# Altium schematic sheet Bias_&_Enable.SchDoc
size 431 x 279 mm; Date: Not shown in title block; ApprovedBy: Not shown in title block; CheckedBy: Not shown in title block; Author: Not shown in title block; CompanyName: Not shown in title block; Engineer: Not shown in title block; Organization: Not shown in title block; Address1: Not shown in title block; Address2: Not shown in title block; Address3: Not shown in title block; Address4: Not shown in title block; DocumentNumber: 3; Revision: Use project parameter SCH_Rev; SheetNumber: 4; SheetTotal: 4; PageSetup: Record=PageOptions¦CenterHorizontal=True¦CenterVertical=True¦PrintScale=1.00¦XCorrection=1.00¦YCorrection=1.00¦PrintKind=0¦BorderSize=5000000¦LeftOffset=0¦BottomOffset=0¦Orientation=2¦PaperLength=1000¦PaperWidth=1000¦Scale=100¦PaperSource=15¦PrintQuality=600¦MediaType=1¦DitherType=10¦PaperKind=Letter¦PrintScaleMode=1
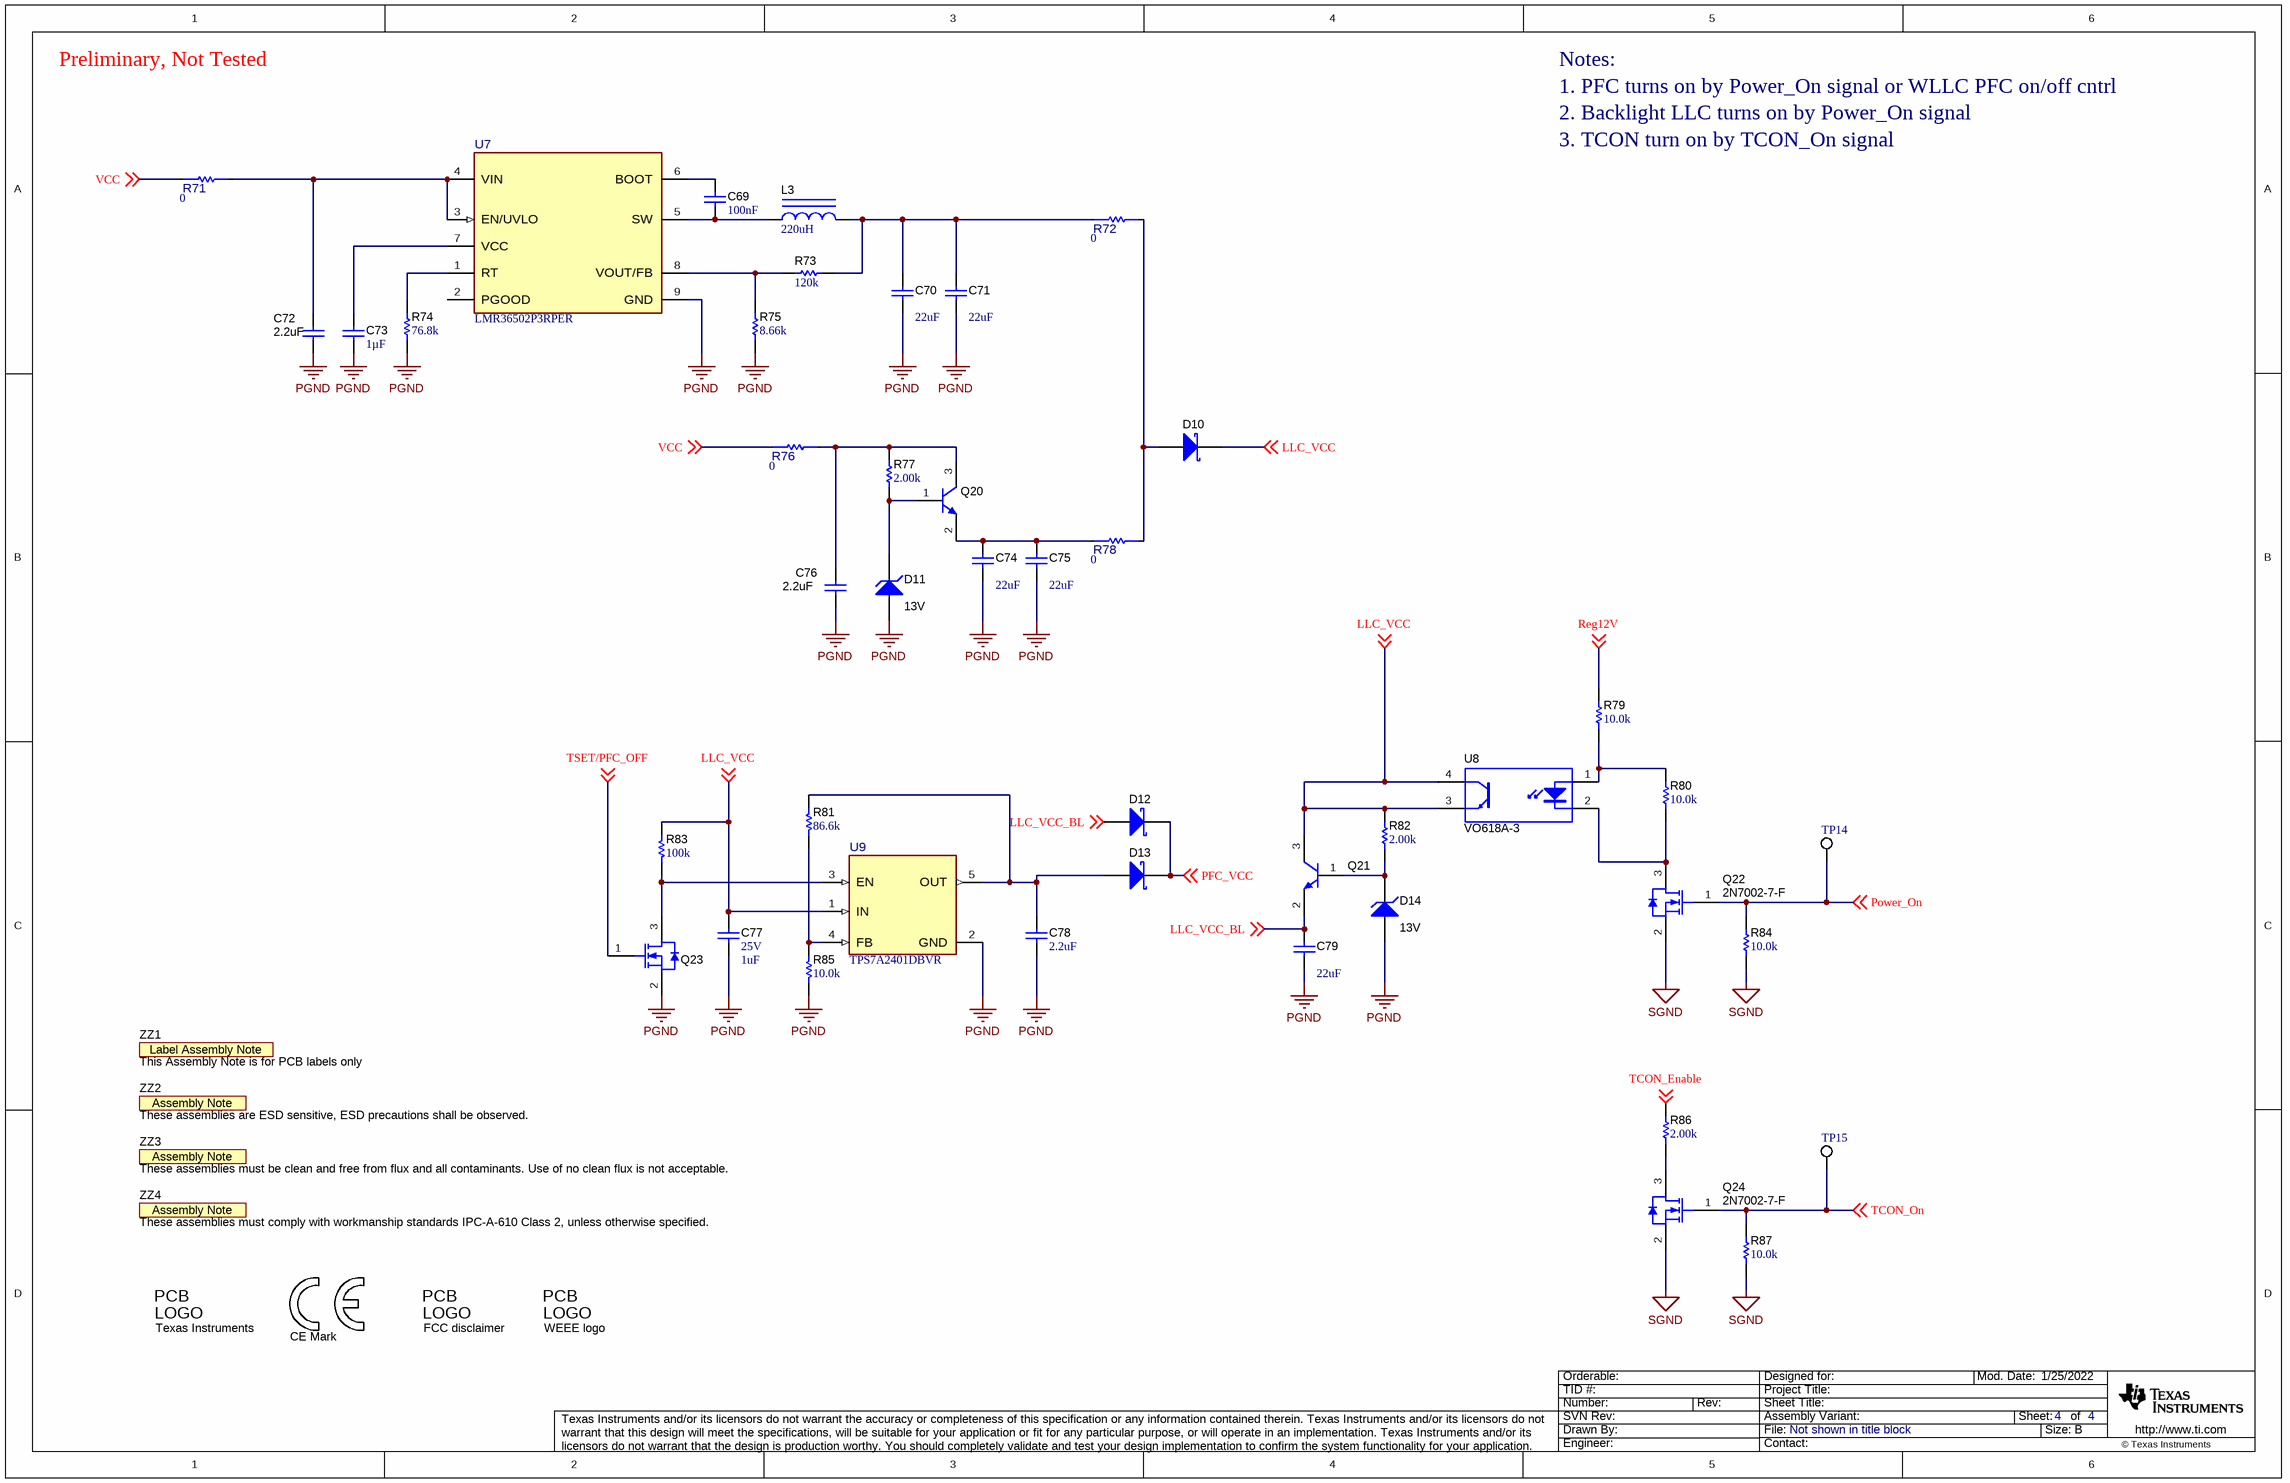
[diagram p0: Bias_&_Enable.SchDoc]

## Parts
C69  Cap_F: 100nF  [0603]  (hidden comment: C0603X104K3RACTU)
C70  ValueDisplayed: 22uF  [1210_270]  (hidden comment: GRM32ER61E226KE15L)
C71  ValueDisplayed: 22uF  [1210_270]  (hidden comment: GRM32ER61E226KE15L)
C72  ValueDisplayed: 2.2uF  [0805L]  (hidden comment: C2012X7R1V225K085AC)
C73  Cap_F: 1µF  [0603]  (hidden comment: C1608X7R1V105K080AC)
C74  ValueDisplayed: 22uF  [1210_270]  (hidden comment: GRM32ER61E226KE15L)
C75  ValueDisplayed: 22uF  [1210_270]  (hidden comment: GRM32ER61E226KE15L)
C76  ValueDisplayed: 2.2uF  [0805L]  (hidden comment: C2012X7R1V225K085AC)
C77  VDC_V: 25V  ValueDisplayed: 1uF  [0603]  (hidden comment: C1608X5R1E105K080AC)
C78  ValueDisplayed: 2.2uF  [0805_HV]  (hidden comment: Capacitor)
C79  ValueDisplayed: 22uF  [1210_270]  (hidden comment: GRM32ER61E226KE15L)
D10  BAT54WS-7-F  [SOD-323]  (value not drawn)
D11  value 13V  [SOD-123]  (hidden comment: MMSZ5243B-7-F)
D12  BAT54WS-7-F  [SOD-323]  (value not drawn)
D13  BAT54WS-7-F  [SOD-323]  (value not drawn)
D14  value 13V  [SOD-123]  (hidden comment: MMSZ5243B-7-F)
L3  ValueDisplayed: 220uH  [MSS5121]  (hidden comment: MSS5121-224MLB)
Logo1  CE Mark  [CE_Mark_5mm]  (no BOM)
Logo2  Texas Instruments  [TI_Stacked_Overlay_Small]  (no BOM)
Logo3  FCC disclaimer  [FCC_disclaimer]  (no BOM)
Logo4  WEEE logo  [WEEE_Minimum]  (no BOM)
Q20  MMBTA05LT1G  [SOT-23]  (value not drawn)
Q21  MMBTA05LT1G  [SOT-23]  (value not drawn)
Q22  2N7002-7-F  [SOT-23]
Q23  2N7002-7-F  [SOT-23]  (value not drawn)
Q24  2N7002-7-F  [SOT-23]
R71  value 0  [FP-RMCF1206ZT0R00_1206-MFG]  (hidden comment: RMCF1206ZT0R00)
R72  value 0  [FP-RMCF1206ZT0R00_1206-MFG]  (hidden comment: RMCF1206ZT0R00)
R73  ValueDisplayed: 120k  [0603]  (hidden comment: RC0603FR-07120KL)
R74  ValueDisplayed: 76.8k  [0603]  (hidden comment: RC0603FR-0776K8L)
R75  ValueDisplayed: 8.66k  [0603]  (hidden comment: RC0603FR-078K66L)
R76  value 0  [FP-RMCF1206ZT0R00_1206-MFG]  (hidden comment: RMCF1206ZT0R00)
R77  ValueDisplayed: 2.00k  [0603]  (hidden comment: RC0603FR-072KL)
R78  value 0  [FP-RMCF1206ZT0R00_1206-MFG]  (hidden comment: RMCF1206ZT0R00)
R79  ValueDisplayed: 10.0k  [0603]  (hidden comment: M55342K12B10E0T)
R80  ValueDisplayed: 10.0k  [0603]  (hidden comment: M55342K12B10E0T)
R81  ValueDisplayed: 86.6k  [0603]  (hidden comment: RC0603FR-0786K6L)
R82  ValueDisplayed: 2.00k  [0603]  (hidden comment: RC0603FR-072KL)
R83  ValueDisplayed: 100k  [0603]  (hidden comment: RC0603FR-07100KL)
R84  ValueDisplayed: 10.0k  [0603]  (hidden comment: M55342K12B10E0T)
R85  ValueDisplayed: 10.0k  [0603]  (hidden comment: M55342K12B10E0T)
R86  ValueDisplayed: 2.00k  [0603]  (hidden comment: RC0603FR-072KL)
R87  ValueDisplayed: 10.0k  [0603]  (hidden comment: M55342K12B10E0T)
TP14  5012  [Keystone5012]  (value not drawn)
TP15  5012  [Keystone5012]  (value not drawn)
U7  LMR36502P3RPER  [RPE0009B-MFG]
U8  VO618A-3  [DIP-4]
U9  TPS7A2401DBVR  [DBV0005A-MFG]
ZZ1  This Assembly Note is for PCB labels only  [AssemblyNoteLabel]  (no BOM)
ZZ2  These assemblies are ESD sensitive, ESD precautions shall be observed.  [AssemblyNote]  (no BOM)
ZZ3  These assemblies must be clean and free from flux and all contaminants. Use of no clean flux is not acceptable.  [AssemblyNote]  (no BOM)
ZZ4  These assemblies must comply with workmanship standards IPC-A-610 Class 2, unless otherwise specified.  [AssemblyNote]  (no BOM)

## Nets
PGND: C70.2 C71.2 C72.2 C73.2 C74.2 C75.2 C76.2 C77.2 C78.1 C79.2 D11.2(A) D14.2(A) Q23.2(S) R74.1 R75.1 R85.1 U7.9(GND) U9.2(GND)
SGND: Q22.2(S) Q24.2(S) R84.1 R87.1
LLC_VCC: C77.1 D10.1(K) Q21.3(C) R82.2 R83.2 U8.3(E) U8.4(C) U9.1(IN) ; off-sheet LLC_VCC
LLC_VCC_BL: C79.1 D12.2(A) Q21.2(E) ; off-sheet LLC_VCC_BL
PFC_VCC: D12.1(K) D13.1(K) ; off-sheet PFC_VCC
Power_On: Q22.1(G) R84.2 TP14.1 ; off-sheet Power_On
Reg12V: R79.2 ; off-sheet Reg12V
TCON_Enable: R86.2 ; off-sheet TCON_Enable
TCON_On: Q24.1(G) R87.2 TP15.1 ; off-sheet TCON_On
TSET/PFC_OFF: Q23.1(G) ; off-sheet TSET/PFC_OFF
VCC: R71.1 R76.1 ; off-sheet VCC
NetC69_1: C69.1 U7.6(BOOT)
NetC69_2: C69.2 L3.1 U7.5(SW)
NetC70_1: C70.1 C71.1 L3.2 R72.1 R73.2
NetC72_1: C72.1 R71.2 U7.3(EN/UVLO) U7.4(VIN)
NetC73_1: C73.1 U7.7(VCC)
NetC74_1: C74.1 C75.1 Q20.2(E) R78.1
NetC76_1: C76.1 Q20.3(C) R76.2 R77.2
NetC78_2: C78.2 D13.2(A) R81.1 U9.5(OUT)
NetD10_2: D10.2(A) R72.2 R78.2
NetD11_1: D11.1(K) Q20.1(B) R77.1
NetD14_1: D14.1(K) Q21.1(B) R82.1
NetQ22_3: Q22.3(D) R80.1 U8.2(K)
NetQ23_3: Q23.3(D) R83.1 U9.3(EN)
NetQ24_3: Q24.3(D) R86.1
NetR73_1: R73.1 R75.2 U7.8(VOUT/FB)
NetR74_2: R74.2 U7.1(RT)
NetR79_1: R79.1 R80.2 U8.1(A)
NetR81_2: R81.2 R85.2 U9.4(FB)

Not connected (* = marked no-connect by the designer): U7 2(PGOOD)

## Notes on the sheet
- Preliminary, Not Tested
- Notes:
- 1. PFC turns on by Power_On signal or WLLC PFC on/off cntrl
- 2. Backlight LLC turns on by Power_On signal
- 3. TCON turn on by TCON_On signal

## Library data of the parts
C69 = CMP-0006979-5: CAP, CERM, 0.1 uF, 25 V, +/- 10%, X7R, 0603; Manufacturer: Kemet; TaMin_C: -55°C; Polarized: N; SizeAreaWB_mm2: 4.68; Value1: Unknown; U/M: EA; Value: 0.1uF; TaMax_C: 125°C; SizeZ_mm: 1; SizeX_mm: 1.6; SizeY_mm: 0.8; Value2: 25V; SizeArea_mm2: 1.28; AEC Category: Q200
C70 C71 C74 C75 C79 = CMP-0009213-2: CAP, CERM, 22 uF, 25 V, +/- 10%, X5R, 1210; Manufacturer: MuRata; TaMin_C: -55°C; ESR_ohm: 2m; Polarized: N; SizeAreaWB_mm2: 14.7; Value1: 0.002 ohm; U/M: EA; Value: 22uF; TaMax_C: 85°C; SizeZ_mm: 2.7; SizeX_mm: 3.2; SizeY_mm: 2.5; Cap_Case: 1210; Value2: 25V; SizeArea_mm2: 8; Cap_F: 22µF; IRMS_A: 3.67A; AEC Category: Q200
C72 C76 = CMP-0007883-2: CAP, CERM, 2.2 uF, 35 V, +/- 10%, X7R, 0805; Manufacturer: TDK; TaMin_C: -55°C; Polarized: N; SizeAreaWB_mm2: 6.75; Value1: Unknown; U/M: EA; Value: 2.2uF; TaMax_C: 125°C; SizeZ_mm: 1.45; SizeX_mm: 2; SizeY_mm: 1.25; Cap_Case: 0805; Value2: 35V; SizeArea_mm2: 2.5; CompType: Capacitor; Cap_F: 2.2µF; AEC Category: Q200
C73 = CMP-0007052-4: CAP, CERM, 1 uF, 35 V, +/- 10%, X7R, 0603; Manufacturer: TDK; TaMin_C: -55°C; Polarized: N; SizeAreaWB_mm2: 4.68; Value1: Unknown; U/M: EA; Value: 1uF; TaMax_C: 125°C; SizeZ_mm: 1; SizeX_mm: 1.6; SizeY_mm: 0.8; Value2: 35V; SizeArea_mm2: 1.28; AEC Category: Q200
C77 = CMP-0007006-5: CAP, CERM, 1 uF, 25 V, +/- 10%, X5R, 0603; Manufacturer: TDK; TaMin_C: -55°C; Polarized: N; SizeAreaWB_mm2: 4.68; Value1: Unknown; U/M: EA; Value: 1uF; TaMax_C: 85°C; SizeZ_mm: 1; SizeX_mm: 1.6; SizeY_mm: 0.8; SizeArea_mm2: 1.28; Cap_F: 1µF; AEC Category: Q200
C78 = CMP-0007877-2: CAP, CERM, 2.2 uF, 50 V, +/- 10%, X7R, 0805; PartNumber: C2012X7R1H225K125AC; Manufacturer: TDK; Polarized: N; Value: 2.2uF; U/M: EA; Cap_F: 2.2µF; ESR_ohm: 3.66m; Value1: 0.00366 ohm; VDC_V: 50V; IRMS_A: 3.41207A; TaMin_C: -55°C; TaMax_C: 125°C; Cap_Case: 0805; SizeArea_mm2: 2.5; SizeAreaWB_mm2: 6.75; SizeX_mm: 2; SizeY_mm: 1.25; SizeZ_mm: 1.45; AEC Category: Q200
D10 D12 D13 = CMP-0028458-2: Diode, Schottky, 30 V, 0.2 A, SOD-323; Manufacturer: Diodes Inc.; SizeArea_mm2: 3.645; Green_Lifecycle: Active; Io_A: 200mA; TJmax_C: 125°C; Value2: 0.7V; Vf_V: 700mV; Green_REACh: Passed; Value1: 0.2A; Vr_V: 30V; AEC Category: Q101; SizeAreaWB_mm2: 8.695; SizeY_mm: 1.35; Value: 30V; SizeX_mm: 2.7; SizeZ_mm: 1
D11 D14 = CMP-0005752-4: Diode, Zener, 13 V, 500 mW, SOD-123; Manufacturer: Diodes Inc.; Value1: 0.5W; SizeAreaWB_mm2: 13.095; RJA_CperW: 350; AEC Category: Q101; SizeZ_mm: 1.35; SizeX_mm: 3.85; Power_W: 500mW; SizeArea_mm2: 6.545; SizeY_mm: 1.7
L3 = CMP-0061952-2: Inductor, Shielded Drum Core, Ferrite, 220 uH, 0.25 A, 3.1 ohm, SMD; Manufacturer: Coilcraft; Isat: 0.25A @ 30% inductance drop; Irms: 0.29A @ 40C rise; Green_Lifecycle: Not Set; SizeAreaWB_mm2: 54.76; DCR_ohm: 3.1; Green_REACh: Incomplete; Value1: 3.1 ohm; Value: 220uH; Imax_A: 2.5dA; SizeZ_mm: 2.2; SizeX_mm: 5.4; Value2: 0.25A; SizeArea_mm2: 29.16; Ind_H: 220µH; AEC Category: Q200
Logo1 = CMP-0074844-1: SymbolCreator: a0412235
Logo2 = CMP-0074838-1: Texas Instrument Corporate Signature; SymbolCreator: a0412235; Lib Reference: TI_Logo; Library Reference: Logo
Logo3 = CMP-0074847-1: FCC_disclaimer; Library Reference: Logo
Logo4 = CMP-0074769-1
Q20 Q21 = CMP-0000488-2: Transistor, NPN, 60 V, 0.5 A, AEC-Q101, SOT-23; Manufacturer: ON Semiconductor; TaMax_C: 150°C; Value1: 0.5 A; Vcesat1_V: 2.5dV; SizeX_mm: 2.5; SizeY_mm: 3; TaMin_C: -55°C; IcRated_A: 5dA; CompType: BJT; SizeZ_mm: 1.1; AEC Qualified: Y; Value: 60 V; SizeArea_mm2: 7.5; NPN: 1; Vceo_V: 60V; PNP: 0; AEC Category: Q101; SizeAreaWB_mm2: 14; U/M: EA
Q22-Q24 = CMP-0000769-1: MOSFET, N-CH, 60 V, 0.17 A, SOT-23; Alternate Manufacturer: None; Manufacturer: Diodes Inc.; SizeZ_mm: 1.1; ChType: N; Value2: 223 nC; Value1: 7; VdsMax_V: 60V; SizeX_mm: 2.5; SizeY_mm: 3; Vgs_V: 20V; Value: 60V; Rdson45_ohm: 7.5; AEC Category: Q101; IdsMax_A: 1.7dA; SizeAreaWB_mm2: 14; U/M: EA; QgTyp_nC: 223
R71 R72 R76 R78 = CMP-0093609-1: 0Ω ±0 0.25W 1206 Thick Film Chip Resistor AEC-Q200 compliant; Manufacturer: Stackpole Electronics; AEC Qualified: Yes; VDC_V: 200V; AEC Grade: Grade 0; Power_W: 250mW; SizeZ_mm: 0.7mm
R73 = CMP-0022768-4: RES, 120 k, 1%, 0.1 W, 0603; Manufacturer: Yageo; Power_W: 100mW; TempCo: 100 ppm/C; Value: 120k; SizeX_mm: 1.6; SizeY_mm: 0.8; SizeZ_mm: 1; Value2: 0.1W; SizeArea_mm2: 1.28; AEC Qualified: N; VDC_V: 75V; AEC Category: Q200; SizeAreaWB_mm2: 4.68
R74 = CMP-0023271-5: RES, 76.8 k, 1%, 0.1 W, 0603; Manufacturer: Yageo; Power_W: 100mW; TempCo: 100 ppm/C; Value_Code: 76k8; Value: 76.8k; EIA_Code: E96; SizeX_mm: 1.6; SizeY_mm: 0.8; SizeZ_mm: 1; Value2: 0.1W; SizeArea_mm2: 1.28; AEC Qualified: N; VDC_V: 75V; AEC Category: Q200; SizeAreaWB_mm2: 4.68
R75 = CMP-0023310-5: RES, 8.66 k, 1%, 0.1 W, 0603; Manufacturer: Yageo; Power_W: 100mW; TempCo: 100 ppm/C; Value_Code: 8k66; Value: 8.66k; EIA_Code: E96; SizeX_mm: 1.6; SizeY_mm: 0.8; SizeZ_mm: 1; Value2: 0.1W; SizeArea_mm2: 1.28; AEC Qualified: N; VDC_V: 75V; AEC Category: Q200; SizeAreaWB_mm2: 4.68
R77 R82 R86 = CMP-0023000-5: RES, 2.00 k, 1%, 0.1 W, 0603; Manufacturer: Yageo; Power_W: 100mW; TempCo: 100 ppm/C; Value_Code: 2k00; Value: 2.00k; EIA_Code: E96; Res_ohm: 2k; SizeX_mm: 1.6; SizeY_mm: 0.8; SizeZ_mm: 1; Value2: 0.1W; SizeArea_mm2: 1.28; AEC Qualified: N; VDC_V: 75V; AEC Category: Q200; SizeAreaWB_mm2: 4.68
R79 R80 R84 R85 R87 = CMP-0080488-1: RES, 10.0 k, 1%, 0.1 W, 0603; Manufacturer: TT Electronics/IRC; Power_W: 100mW; TempCo: 100 ppm/C; SizeAreaWB_mm2: 4.68; Value_Code: 10k0; Value: 10.0k; EIA_Code: E96; Res_ohm: 10k; SizeX_mm: 1.6; SizeY_mm: 0.8; SizeZ_mm: 1; Value2: 0.1W; SizeArea_mm2: 1.28; AEC Qualified: N; AEC Category: Q200
R81 = CMP-0023301-5: RES, 86.6 k, 1%, 0.1 W, 0603; Manufacturer: Yageo; Power_W: 100mW; TempCo: 100 ppm/C; Value_Code: 86k6; Value: 86.6k; EIA_Code: E96; SizeX_mm: 1.6; SizeY_mm: 0.8; SizeZ_mm: 1; Value2: 0.1W; SizeArea_mm2: 1.28; AEC Qualified: N; VDC_V: 75V; AEC Category: Q200; SizeAreaWB_mm2: 4.68
R83 = CMP-0022735-5: RES, 100 k, 1%, 0.1 W, 0603; Manufacturer: Yageo; Power_W: 100mW; TempCo: 100 ppm/C; Value: 100k; EIA_Code: E96; SizeX_mm: 1.6; SizeY_mm: 0.8; SizeZ_mm: 1; Value2: 0.1W; SizeArea_mm2: 1.28; AEC Qualified: N; VDC_V: 75V; AEC Category: Q200; SizeAreaWB_mm2: 4.68
TP14 TP15 = CMP-0055149-2: Test Point, Multipurpose, White, TH; Manufacturer: Keystone Electronics; ContactFinish: Silver; CT: TRUE; CNHeader: FALSE; Green_Lifecycle: Active; Green_REACh: Passed
U7 = CMP-0120075-1: 3-V to 65-V, 150-mA Wide VIN Synchronous Buck Converter Optimized for Size and Light Load Efficiency; Manufacturer: Texas Instruments; SizeZ_mm: 1mm; AEC Qualified: No; Max Duty Cycle: 98%; Max Supply Voltage: 65V; Min Supply Voltage: 3.6V; Nominal Supply Current: 0.672-18uA; Number Of Outputs: 1; Output Type: Fixed,AdjustableProgrammable; Output Voltage: 3.3/1-16V; Standoff Height: 0mm; Switching Frequency: 0.2-2.2MHz; TJmax_C: +150°C
U8 = CMP-0083653-1: Optocoupler, 5.3 kV, 100-200% CTR, SMT; Manufacturer: Vishay-Semiconductor; CTR (Max): 200%; SizeAreaWB_mm2: 71.064; CTR (Min): 100%; SizeZ_mm: 5; SizeX_mm: 8.8; SizeY_mm: 4.58; SizeArea_mm2: 40.304; Voltage_Isolation_Vrms: 5.3kV
U9 = CMP-0089843-1: Linear Voltage Regulator IC 1 Output 200mA SOT-23-5; Manufacturer: Texas Instruments; Output Type: AdjustableProgrammable; Accuracy Percentage: 2%; AEC Qualified: No; Max Supply Voltage: 18V; Dropout Voltage: 160mV; SizeZ_mm: 1.45mm; Output Voltage: 1.24-17.75V; Min Supply Voltage: 2.4V; TJmax_C: +125°C; Nominal Supply Current: 2uA; Number Of Outputs: 1; Standoff Height: 0mm
ZZ1 = CMP-0003616-3
ZZ2 = CMP-0077236-1
ZZ3 = CMP-0077237-1
ZZ4 = CMP-0077238-1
